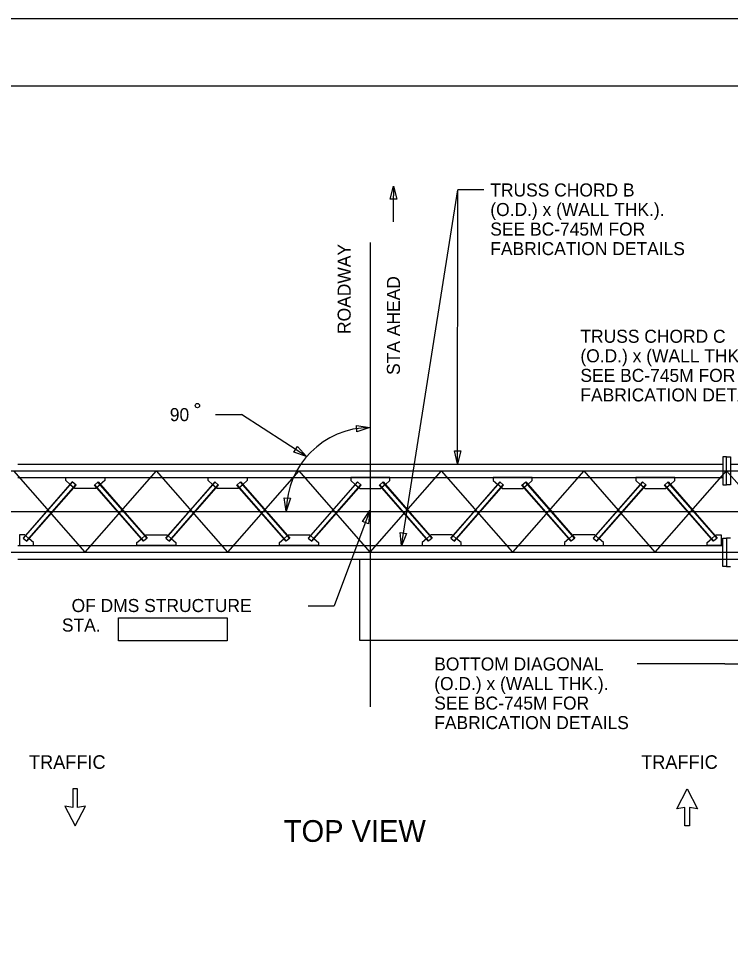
# Model space of a CAD drawing. Extents: x 3831399 to 3833095, y 499014 to 500202.
# Drawn here: x 3832461.1 to 3832620, y 499994 to 500202 of the extents above; entities that cross this region are included whole.
import ezdxf

# ---------------------------------------------------------------- set-up
doc = ezdxf.new("R2010")
doc.units = 0
for name, color, linetype in [('0-sign', 7, 'Continuous'), ('0-truss', 7, 'Continuous'), ('2', 7, 'Continuous'), ('CenterLine', 7, 'Continuous'), ('Default', 7, 'Continuous'), ('DIM TXT', 7, 'Continuous'), ('PLT-BNDY', 7, 'Continuous')]:
    doc.layers.add(name, color=color, linetype=linetype)

msp = doc.modelspace()

# ---------------------------------------------------------------- linework, layer by layer
at = {"layer": '0-sign'}
for p, q in [((3832537.29, 500081.37), (3832650.95, 500081.37)), ((3832537.29, 500063.18), (3832537.29, 500081.37)), ((3832650.95, 500063.18), (3832537.29, 500063.18))]:
    msp.add_line(p, q, dxfattribs=at)
at = {"layer": '0-truss'}
for p, q in [((3832460.9, 500102.58), (3832618.33, 500102.58)), ((3832619.18, 500104.22), (3832618.33, 500104.22)), ((3832618.33, 500104.22), (3832618.33, 500097.92)), ((3832619.18, 500097.92), (3832619.18, 500104.22)), ((3832619.18, 500104.22), (3832620.03, 500104.22)), ((3832619.18, 500097.92), (3832619.18, 500104.22)), ((3832620.03, 500104.22), (3832620.03, 500097.92)), ((3832620.03, 500102.58), (3832750.49, 500102.58)), ((3832460.9, 500099.55), (3832618.33, 500099.55)), ((3832473.08, 500098.61), (3832462.1, 500086.06)), ((3832462.16, 500086.01), (3832473.14, 500098.56)), ((3832472.59, 500098.04), (3832471.6, 500098.9)), ((3832473.9, 500097.89), (3832473.08, 500098.61)), ((3832478.02, 500097.89), (3832478.84, 500098.61)), ((3832489.76, 500086.01), (3832478.78, 500098.56)), ((3832478.84, 500098.61), (3832489.82, 500086.06)), ((3832480.32, 500098.9), (3832479.33, 500098.04)), ((3832504.91, 500098.61), (3832493.93, 500086.06)), ((3832493.99, 500086.01), (3832504.97, 500098.56)), ((3832504.41, 500098.04), (3832503.43, 500098.9)), ((3832505.73, 500097.89), (3832504.91, 500098.61)), ((3832509.84, 500097.89), (3832510.66, 500098.61)), ((3832521.58, 500086.01), (3832510.6, 500098.56)), ((3832510.66, 500098.61), (3832521.64, 500086.06)), ((3832512.14, 500098.9), (3832511.16, 500098.04)), ((3832536.74, 500098.61), (3832525.76, 500086.06)), ((3832525.81, 500086.01), (3832536.79, 500098.56)), ((3832535.26, 500098.9), (3832536.24, 500098.04)), ((3832537.56, 500097.89), (3832536.74, 500098.61)), ((3832541.67, 500097.89), (3832542.49, 500098.61)), ((3832553.41, 500086.01), (3832542.43, 500098.56)), ((3832542.49, 500098.61), (3832553.47, 500086.06)), ((3832542.99, 500098.04), (3832543.97, 500098.9)), ((3832568.56, 500098.61), (3832557.58, 500086.06)), ((3832557.64, 500086.01), (3832568.62, 500098.56)), ((3832567.08, 500098.9), (3832568.07, 500098.04)), ((3832569.38, 500097.89), (3832568.56, 500098.61)), ((3832573.5, 500097.89), (3832574.32, 500098.61)), ((3832585.24, 500086.01), (3832574.26, 500098.56)), ((3832574.32, 500098.61), (3832585.3, 500086.06)), ((3832574.81, 500098.04), (3832575.8, 500098.9)), ((3832600.39, 500098.61), (3832589.41, 500086.06)), ((3832589.47, 500086.01), (3832600.45, 500098.56)), ((3832598.91, 500098.9), (3832599.9, 500098.04)), ((3832601.21, 500097.89), (3832600.39, 500098.61)), ((3832605.32, 500097.89), (3832606.14, 500098.61)), ((3832617.07, 500086.01), (3832606.09, 500098.56)), ((3832606.14, 500098.61), (3832617.12, 500086.06)), ((3832606.64, 500098.04), (3832607.63, 500098.9)), ((3832462.86, 500085.39), (3832473.84, 500097.94)), ((3832462.92, 500085.34), (3832473.9, 500097.89)), ((3832472.59, 500098.04), (3832473.41, 500097.32)), ((3832473.62, 500097.14), (3832473.41, 500097.32)), ((3832489, 500085.34), (3832478.02, 500097.89)), ((3832489.05, 500085.39), (3832478.07, 500097.94)), ((3832478.51, 500097.32), (3832478.3, 500097.14)), ((3832478.51, 500097.32), (3832479.33, 500098.04)), ((3832494.69, 500085.39), (3832505.67, 500097.94)), ((3832494.75, 500085.34), (3832505.73, 500097.89)), ((3832504.41, 500098.04), (3832505.23, 500097.32)), ((3832505.45, 500097.14), (3832505.23, 500097.32)), ((3832520.82, 500085.34), (3832509.84, 500097.89)), ((3832520.88, 500085.39), (3832509.9, 500097.94)), ((3832510.34, 500097.32), (3832510.12, 500097.14)), ((3832510.34, 500097.32), (3832511.16, 500098.04)), ((3832526.52, 500085.39), (3832537.5, 500097.94)), ((3832526.58, 500085.34), (3832537.56, 500097.89)), ((3832536.24, 500098.04), (3832537.06, 500097.32)), ((3832537.06, 500097.32), (3832537.27, 500097.14)), ((3832552.65, 500085.34), (3832541.67, 500097.89)), ((3832552.71, 500085.39), (3832541.73, 500097.94)), ((3832541.95, 500097.14), (3832542.17, 500097.32)), ((3832542.99, 500098.04), (3832542.17, 500097.32)), ((3832558.35, 500085.39), (3832569.33, 500097.94)), ((3832558.4, 500085.34), (3832569.38, 500097.89)), ((3832568.89, 500097.32), (3832568.07, 500098.04)), ((3832568.89, 500097.32), (3832569.1, 500097.14)), ((3832584.48, 500085.34), (3832573.5, 500097.89)), ((3832584.54, 500085.39), (3832573.56, 500097.94)), ((3832573.78, 500097.14), (3832573.99, 500097.32)), ((3832574.81, 500098.04), (3832573.99, 500097.32)), ((3832590.17, 500085.39), (3832601.15, 500097.94)), ((3832590.23, 500085.34), (3832601.21, 500097.89)), ((3832600.72, 500097.32), (3832599.9, 500098.04)), ((3832600.72, 500097.32), (3832600.93, 500097.14)), ((3832616.3, 500085.34), (3832605.32, 500097.89)), ((3832616.36, 500085.39), (3832605.38, 500097.94)), ((3832605.61, 500097.14), (3832605.82, 500097.32)), ((3832606.64, 500098.04), (3832605.82, 500097.32)), ((3832618.33, 500097.92), (3832619.18, 500097.92)), ((3832620.03, 500097.92), (3832619.18, 500097.92)), ((3832462.38, 500086.81), (3832461.28, 500086.81)), ((3832461.28, 500086.81), (3832461.28, 500086.81)), ((3832461.28, 500086.81), (3832461.28, 500084.4)), ((3832462.1, 500086.06), (3832462.92, 500085.34)), ((3832462.6, 500086.63), (3832462.38, 500086.81)), ((3832462.6, 500086.63), (3832463.42, 500085.91)), ((3832464.4, 500085.05), (3832463.42, 500085.91)), ((3832487.52, 500085.05), (3832488.5, 500085.91)), ((3832488.5, 500085.91), (3832489.32, 500086.63)), ((3832489.82, 500086.06), (3832489, 500085.34)), ((3832489.32, 500086.63), (3832489.53, 500086.81)), ((3832493.93, 500086.06), (3832494.75, 500085.34)), ((3832494.21, 500086.81), (3832494.42, 500086.63)), ((3832494.42, 500086.63), (3832495.24, 500085.91)), ((3832495.24, 500085.91), (3832496.23, 500085.05)), ((3832519.34, 500085.05), (3832520.33, 500085.91)), ((3832520.33, 500085.91), (3832521.15, 500086.63)), ((3832521.64, 500086.06), (3832520.82, 500085.34)), ((3832521.15, 500086.63), (3832521.36, 500086.81)), ((3832525.76, 500086.06), (3832526.58, 500085.34)), ((3832526.04, 500086.81), (3832526.25, 500086.63)), ((3832526.25, 500086.63), (3832527.07, 500085.91)), ((3832527.07, 500085.91), (3832528.06, 500085.05)), ((3832552.15, 500085.91), (3832551.17, 500085.05)), ((3832552.97, 500086.63), (3832552.15, 500085.91)), ((3832553.47, 500086.06), (3832552.65, 500085.34)), ((3832553.19, 500086.81), (3832552.97, 500086.63)), ((3832557.58, 500086.06), (3832558.4, 500085.34)), ((3832558.08, 500086.63), (3832557.87, 500086.81)), ((3832558.9, 500085.91), (3832558.08, 500086.63)), ((3832559.88, 500085.05), (3832558.9, 500085.91)), ((3832583.98, 500085.91), (3832583, 500085.05)), ((3832584.8, 500086.63), (3832583.98, 500085.91)), ((3832585.3, 500086.06), (3832584.48, 500085.34)), ((3832585.02, 500086.81), (3832584.8, 500086.63)), ((3832589.41, 500086.06), (3832590.23, 500085.34)), ((3832589.91, 500086.63), (3832589.69, 500086.81)), ((3832590.73, 500085.91), (3832589.91, 500086.63)), ((3832591.71, 500085.05), (3832590.73, 500085.91)), ((3832614.82, 500085.05), (3832615.81, 500085.91)), ((3832616.63, 500086.63), (3832615.81, 500085.91)), ((3832617.12, 500086.06), (3832616.3, 500085.34)), ((3832616.63, 500086.63), (3832616.84, 500086.81)), ((3832616.84, 500086.81), (3832617.95, 500086.81)), ((3832617.95, 500086.81), (3832617.95, 500086.81)), ((3832617.95, 500086.81), (3832617.95, 500084.4)), ((3832618.33, 500086.03), (3832619.18, 500086.03)), ((3832618.33, 500079.73), (3832618.33, 500086.03)), ((3832620.03, 500086.03), (3832619.18, 500086.03)), ((3832619.18, 500086.03), (3832619.18, 500079.73)), ((3832619.18, 500086.03), (3832619.18, 500079.73)), ((3832460.9, 500084.4), (3832618.33, 500084.4)), ((3832460.9, 500081.37), (3832618.33, 500081.37)), ((3832619.18, 500079.73), (3832618.33, 500079.73)), ((3832619.18, 500079.73), (3832620.03, 500079.73))]:
    msp.add_line(p, q, dxfattribs=at)
for points in [[(3832471.6, 500098.9), (3832471.6, 500099.55), (3832480.32, 500099.55), (3832480.32, 500098.9)], [(3832503.43, 500098.9), (3832503.43, 500099.55), (3832512.14, 500099.55), (3832512.14, 500098.9)], [(3832543.97, 500098.9), (3832543.97, 500099.55), (3832535.26, 500099.55), (3832535.26, 500098.9)], [(3832575.8, 500098.9), (3832575.8, 500099.55), (3832567.08, 500099.55), (3832567.08, 500098.9)], [(3832607.63, 500098.9), (3832607.63, 500099.55), (3832598.91, 500099.55), (3832598.91, 500098.9)], [(3832478.3, 500097.14), (3832473.62, 500097.14)], [(3832510.12, 500097.14), (3832505.45, 500097.14)], [(3832537.27, 500097.14), (3832541.95, 500097.14)], [(3832569.1, 500097.14), (3832573.78, 500097.14)], [(3832600.93, 500097.14), (3832605.61, 500097.14)], [(3832489.53, 500086.81), (3832494.21, 500086.81)], [(3832521.36, 500086.81), (3832526.04, 500086.81)], [(3832557.87, 500086.81), (3832553.19, 500086.81)], [(3832589.69, 500086.81), (3832585.02, 500086.81)], [(3832461.28, 500084.4), (3832464.4, 500084.4), (3832464.4, 500085.05)], [(3832496.23, 500085.05), (3832496.23, 500084.4), (3832487.52, 500084.4), (3832487.52, 500085.05)], [(3832528.06, 500085.05), (3832528.06, 500084.4), (3832519.34, 500084.4), (3832519.34, 500085.05)], [(3832551.17, 500085.05), (3832551.17, 500084.4), (3832559.88, 500084.4), (3832559.88, 500085.05)], [(3832583, 500085.05), (3832583, 500084.4), (3832591.71, 500084.4), (3832591.71, 500085.05)], [(3832617.95, 500084.4), (3832614.82, 500084.4), (3832614.82, 500085.05)]]:
    msp.add_lwpolyline(points, dxfattribs=at)
at = {"layer": '2'}
msp.add_line((3832280.16, 500187.03), (3833066.16, 500187.03), dxfattribs=at)
at = {"layer": 'CenterLine'}
for p, q in [((3832539.61, 500152.08), (3832539.61, 500048.39)), ((3832324.19, 500101.07), (3832755.03, 500101.07)), ((3832475.96, 500082.88), (3832460.05, 500101.07)), ((3832475.96, 500082.88), (3832491.87, 500101.07)), ((3832507.79, 500082.88), (3832491.87, 500101.07)), ((3832507.79, 500082.88), (3832523.7, 500101.07)), ((3832539.61, 500082.88), (3832523.7, 500101.07)), ((3832539.61, 500082.88), (3832555.53, 500101.07)), ((3832571.44, 500082.88), (3832555.53, 500101.07)), ((3832571.44, 500082.88), (3832587.35, 500101.07)), ((3832603.27, 500082.88), (3832587.35, 500101.07)), ((3832603.27, 500082.88), (3832619.18, 500101.07)), ((3832635.1, 500082.88), (3832619.18, 500101.07)), ((3832324.19, 500091.98), (3832755.03, 500091.98)), ((3832324.19, 500082.88), (3832755.03, 500082.88))]:
    msp.add_line(p, q, dxfattribs=at)
at = {"layer": 'Default'}
for p, q in [((3832483.41, 500068.22), (3832507.66, 500068.22)), ((3832483.41, 500063.13), (3832483.41, 500068.22)), ((3832507.66, 500068.22), (3832507.66, 500063.13)), ((3832507.66, 500063.13), (3832483.41, 500063.13))]:
    msp.add_line(p, q, dxfattribs=at)
msp.add_circle((3832501.02, 500115.63), 0.487, dxfattribs=at)
at = {"layer": 'DIM TXT'}
for p, q in [((3832544.79, 500164.61), (3832544.79, 500162.49)), ((3832546.56, 500084.3), (3832559.15, 500163.78)), ((3832559.12, 500102.61), (3832559.15, 500163.78)), ((3832564.97, 500163.78), (3832559.15, 500163.78)), ((3832564.97, 500163.78), (3832559.15, 500163.78)), ((3832544.79, 500156.67), (3832544.79, 500162.49)), ((3832505.03, 500113.62), (3832510.85, 500113.62)), ((3832525.39, 500104.3), (3832510.85, 500113.62)), ((3832539.55, 500092.24), (3832531.53, 500070.95)), ((3832525.71, 500070.95), (3832531.53, 500070.95)), ((3832618.78, 500057.95), (3832599.25, 500057.95)), ((3832618.78, 500057.95), (3832624.6, 500057.95)), ((3832474.22, 500030.06), (3832473.17, 500030.06)), ((3832473.17, 500030.06), (3832473.17, 500025.93)), ((3832474.22, 500025.93), (3832474.22, 500030.06)), ((3832608.08, 500025.64), (3832610.4, 500030.06)), ((3832610.4, 500030.06), (3832612.71, 500025.64)), ((3832473.17, 500025.93), (3832471.38, 500026.23)), ((3832471.38, 500026.23), (3832473.69, 500021.81)), ((3832473.69, 500021.81), (3832476.01, 500026.23)), ((3832476.01, 500026.23), (3832474.22, 500025.93)), ((3832609.87, 500025.93), (3832608.08, 500025.64)), ((3832609.87, 500021.81), (3832609.87, 500025.93)), ((3832610.92, 500025.93), (3832610.92, 500021.81)), ((3832612.71, 500025.64), (3832610.92, 500025.93)), ((3832610.92, 500021.81), (3832609.87, 500021.81))]:
    msp.add_line(p, q, dxfattribs=at)
for points in [[(3832544.06, 500161.7), (3832544.79, 500164.61), (3832545.52, 500161.7)], [(3832536.54, 500111.22), (3832539.5, 500110.73), (3832536.65, 500109.77)], [(3832523.34, 500106.49), (3832525.39, 500104.3), (3832522.55, 500105.26)], [(3832559.85, 500105.52), (3832559.12, 500102.61), (3832558.4, 500105.52)], [(3832521.82, 500094.94), (3832520.87, 500092.09), (3832520.37, 500095.05)], [(3832537.85, 500089.77), (3832539.55, 500092.24), (3832539.21, 500089.26)], [(3832547.74, 500087.06), (3832546.56, 500084.3), (3832546.3, 500087.28)]]:
    msp.add_lwpolyline(points, close=True, dxfattribs=at)
msp.add_arc((3832539.5, 500092.09), 18.63, 90, 180, dxfattribs=at)
at = {"layer": 'PLT-BNDY'}
msp.add_lwpolyline([(3832240.16, 500202.03), (3833081.16, 500202.03), (3833081.16, 499608.03), (3832240.16, 499608.03)], close=True, dxfattribs=at)

# ---------------------------------------------------------------- texts
at = {"layer": 'DIM TXT'}
for s, height, p in [('TRUSS CHORD B', 2.9099, (3832566.42, 500162.32)), ('(O.D.) x (WALL THK.).', 2.9099, (3832566.42, 500157.96)), ('SEE BC-745M FOR', 2.9099, (3832566.42, 500153.59)), ('FABRICATION DETAILS', 2.9099, (3832566.42, 500149.23)), ('TRUSS CHORD C', 2.9099, (3832586.54, 500129.66)), ('(O.D.) x (WALL THK.).', 2.9099, (3832586.54, 500125.3)), ('SEE BC-745M FOR', 2.9099, (3832586.54, 500120.93)), ('FABRICATION DETAILS', 2.9099, (3832586.54, 500116.57)), ('90 ', 2.91, (3832494.85, 500112.17)), ('  OF DMS STRUCTURE', 2.9099, (3832470.75, 500069.55)), ('STA.', 2.91, (3832470.75, 500065.19)), ('BOTTOM DIAGONAL', 2.9099, (3832553.9, 500056.5)), ('(O.D.) x (WALL THK.).', 2.9099, (3832553.9, 500052.13)), ('SEE BC-745M FOR', 2.9099, (3832553.9, 500047.77)), ('FABRICATION DETAILS', 2.9099, (3832553.9, 500043.41)), ('TRAFFIC', 3.031, (3832463.4, 500034.54)), ('TRAFFIC', 3.031, (3832600.11, 500034.54)), ('TOP VIEW', 4.85, (3832520.31, 500018.24))]:
    msp.add_text(s, height=height, dxfattribs=at).set_placement(p)
for s, p in [('  ROADWAY', (3832535.24, 500129.46)), (' STA AHEAD', (3832546.24, 500121.4))]:
    msp.add_text(s, height=2.91, rotation=90, dxfattribs=at).set_placement(p)

doc.saveas('drawing.dxf')
